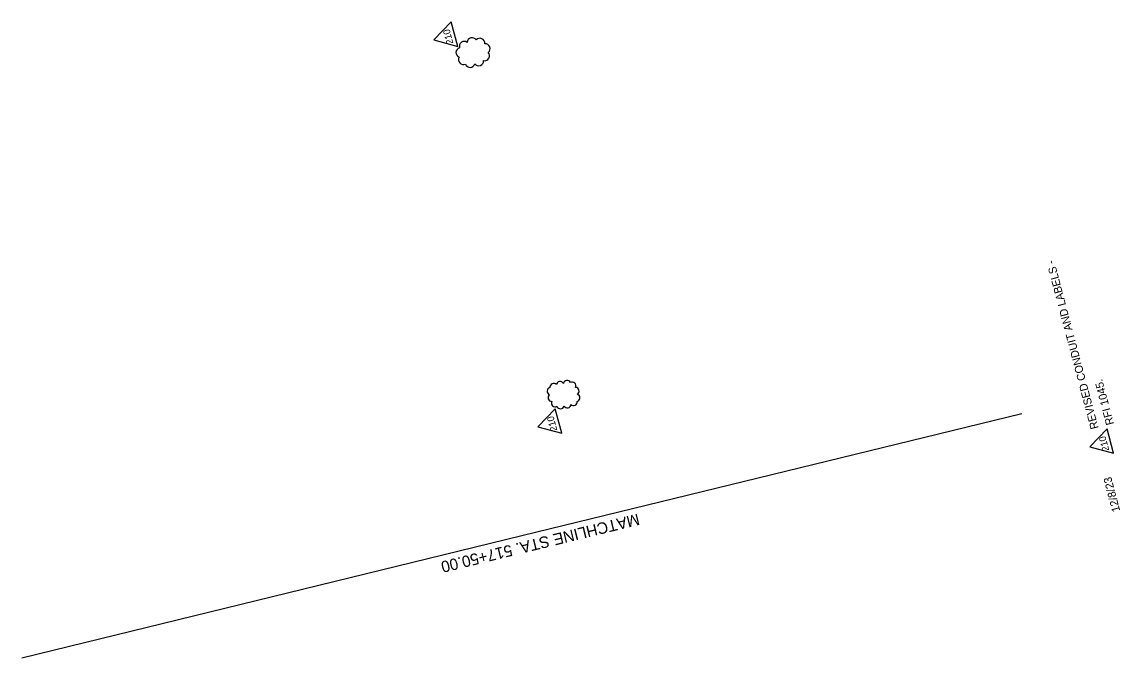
# Model space of a CAD drawing. Extents: x 930394 to 931429, y 627795 to 629076.
# Drawn here: x 930661 to 931429, y 627795 to 628240 of the extents above; entities that cross this region are included whole.
import ezdxf

# ---------------------------------------------------------------- set-up
doc = ezdxf.new("R2010")
doc.units = 0
for name, color, linetype in [('Cloud_dp', 7, 'Continuous'), ('MatchLines_dp', 7, 'Continuous'), ('TextMinor', 7, 'Continuous')]:
    doc.layers.add(name, color=color, linetype=linetype)

msp = doc.modelspace()

# ---------------------------------------------------------------- linework, layer by layer
at = {"layer": 'Cloud_dp'}
for points in [[(930948.85, 628226.94), (930965.6, 628222.46), (930961.08, 628239.52)], [(931021.55, 627956.33), (931038.3, 627951.84), (931033.78, 627968.91)], [(931407.6, 627942.36), (931424.35, 627937.88), (931419.83, 627954.94)]]:
    msp.add_lwpolyline(points, close=True, dxfattribs=at)
for centre, radius, start, end in [((930970.16, 628222.51), 3.44, 53.04833, 198.04833), ((930975.66, 628225.1), 3.44, 32.32565, 177.32565), ((930981.15, 628224.67), 3.44, 353.81142, 138.81142), ((930967.78, 628218.12), 3.44, 105.06755, 250.06755), ((930984.45, 628215.87), 3.44, 257.68737, 42.68737), ((930984.81, 628220.87), 3.44, 309.01859, 94.01859), ((930969.56, 628213.13), 3.44, 149.31832, 294.31832), ((930974.2, 628211.19), 3.44, 200.28185, 345.28185), ((930980.28, 628212.39), 3.44, 217.01058, 2.01058), ((931037.15, 627985.53), 2.6, 27.40438, 172.40438), ((931042.01, 627986.25), 2.6, 24.47009, 169.47009), ((931045.67, 627985.07), 2.6, 334.80665, 119.80665), ((931030.72, 627981.26), 2.6, 104.47212, 249.47212), ((931032.65, 627984.12), 2.6, 42.42065, 187.42065), ((931047.84, 627981.37), 2.6, 300.96574, 85.96574), ((931031.36, 627976.74), 2.6, 126.55496, 271.55496), ((931033.76, 627972.99), 2.6, 153.57972, 298.57972), ((931042.19, 627972.2), 2.6, 210.65669, 355.65669), ((931046.66, 627973.79), 2.6, 223.66484, 8.66484), ((931048.42, 627976.65), 2.6, 288.20425, 73.20425), ((931037.45, 627971.57), 2.6, 199.38715, 344.38715)]:
    msp.add_arc(centre, radius, start, end, dxfattribs=at)
at = {"layer": 'MatchLines_dp'}
msp.add_lwpolyline([(931360.22, 627965.54), (931010.5, 627880.11), (930660.79, 627794.67)], dxfattribs=at)

# ---------------------------------------------------------------- texts
at = {"layer": 'Cloud_dp'}
for p in [(930962.56, 628224.51), (931035.26, 627953.9), (931421.31, 627939.93)]:
    msp.add_text('210', height=4.799, rotation=104.82565, dxfattribs=at).set_placement(p)
at = {"layer": 'MatchLines_dp'}
msp.add_text('MATCHLINE STA. 517+50.00', height=8, rotation=193.7289, dxfattribs=at).set_placement((931091.6, 627895.8))
at = {"layer": 'TextMinor'}
for s, p in [('REVISED CONDUIT AND LABELS - ', (931413.85, 627955.53)), ('RFI 1045.', (931424.68, 627958.4)), ('12/8/23', (931428.97, 627897.64))]:
    msp.add_text(s, height=5.6, rotation=104.82565, dxfattribs=at).set_placement(p)

doc.saveas('drawing.dxf')
